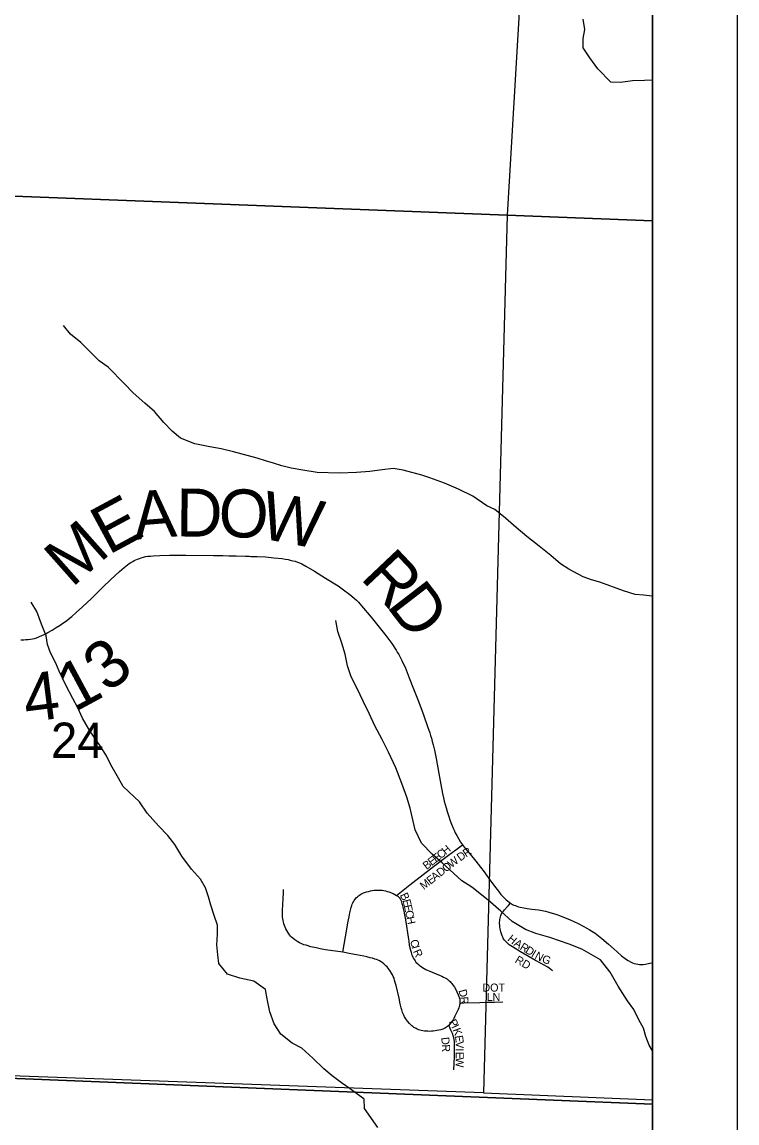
# Model space of a CAD drawing. Extents: x 0 to 34, y 0 to 22.
# Drawn here: x 30.071 to 30.917, y 18.143 to 19.446 of the extents above; entities that cross this region are included whole.
import ezdxf

# ---------------------------------------------------------------- set-up
doc = ezdxf.new("R2010")
doc.units = 0
for name, color, linetype in [('GM_X_Adjacent_County', 7, 'Continuous'), ('GM_X_County', 7, 'Continuous'), ('GM_X_County_Road', 7, 'Continuous'), ('GM_X_Minor_River', 7, 'Continuous'), ('GM_X_Section', 7, 'Continuous'), ('GM_X_Section_Text', 7, 'Continuous'), ('GM_X_Township', 7, 'Continuous'), ('GM_X_Township_Road', 7, 'Continuous'), ('GM_X_Township_Road_Text', 7, 'Continuous'), ('GM_X_Township_Subdivision', 7, 'Continuous'), ('GM_X_Township_Subdivision_Text', 7, 'Continuous'), ('SH_Data', 7, 'Continuous')]:
    doc.layers.add(name, color=color, linetype=linetype)

msp = doc.modelspace()

# ---------------------------------------------------------------- linework, layer by layer
at = {"layer": 'GM_X_Adjacent_County'}
msp.add_lwpolyline([(28.5181, 14.1), (30.8167, 14.1), (30.8167, 20.9), (28.7526, 20.9)], dxfattribs=at)
at = {"layer": 'GM_X_County'}
msp.add_lwpolyline([(28.5181, 14.1), (30.8167, 14.1), (30.8167, 20.9), (28.7526, 20.9)], dxfattribs=at)
at = {"layer": 'GM_X_County_Road'}
for points in [[(30.5918, 18.472), (30.5956, 18.4674), (30.6008, 18.4612), (30.6077, 18.4527), (30.6131, 18.4459), (30.6175, 18.4401), (30.6231, 18.4324), (30.6298, 18.4232), (30.6344, 18.4172), (30.6374, 18.4135), (30.6401, 18.4105), (30.6424, 18.4081), (30.6436, 18.407), (30.645, 18.4059), (30.6472, 18.4042), (30.6489, 18.4031)], [(30.6489, 18.4031), (30.6498, 18.4025), (30.6511, 18.4017), (30.6528, 18.4009), (30.6545, 18.4002), (30.6563, 18.3995), (30.6581, 18.3989), (30.6603, 18.3984), (30.6643, 18.3976), (30.6686, 18.3969), (30.6739, 18.3961), (30.6817, 18.3951), (30.6841, 18.3947), (30.6861, 18.3944), (30.6882, 18.394), (30.6903, 18.3935), (30.6928, 18.3929), (30.6954, 18.3921), (30.7024, 18.39), (30.7066, 18.3885), (30.7113, 18.3867), (30.7187, 18.3837), (30.7288, 18.3791), (30.7347, 18.3761), (30.739, 18.3736), (30.7419, 18.372), (30.745, 18.3701), (30.7487, 18.3675), (30.7527, 18.3645), (30.7569, 18.3612), (30.7645, 18.3546), (30.7713, 18.3486), (30.7748, 18.3454), (30.7802, 18.3409), (30.7843, 18.3377), (30.7859, 18.3366), (30.7879, 18.3353), (30.7905, 18.3338), (30.7931, 18.3327), (30.7952, 18.3319), (30.7972, 18.3314), (30.7993, 18.3309), (30.8014, 18.3306), (30.8036, 18.3304), (30.8058, 18.3305), (30.8084, 18.3308), (30.8137, 18.332), (30.8165, 18.3326), (30.8167, 18.3326)]]:
    msp.add_lwpolyline(points, dxfattribs=at)
at = {"layer": 'GM_X_Minor_River'}
for points in [[(30.8167, 19.3774), (30.8071, 19.377), (30.7931, 19.3765), (30.7787, 19.3744), (30.7673, 19.3747), (30.752, 19.3908), (30.7425, 19.4036), (30.7348, 19.4157), (30.7347, 19.4267), (30.7365, 19.4373), (30.7345, 19.4494)], [(30.3062, 18.941), (30.2929, 18.9432), (30.2751, 18.9468), (30.2584, 18.9534), (30.2485, 18.9617), (30.2385, 18.9722), (30.2274, 18.9849), (30.216, 18.9951), (30.2023, 19.007), (30.1919, 19.0179), (30.1725, 19.0374), (30.1622, 19.0449), (30.1503, 19.0569), (30.1404, 19.0667), (30.1282, 19.0768), (30.1198, 19.0869)], [(30.8167, 18.7665), (30.8165, 18.7665), (30.8059, 18.7676), (30.7964, 18.7686), (30.7824, 18.773), (30.7546, 18.783), (30.7444, 18.7859), (30.7345, 18.7892), (30.7178, 18.7985), (30.7079, 18.8049), (30.6964, 18.8146), (30.6827, 18.8258), (30.6682, 18.837), (30.6556, 18.8479), (30.6427, 18.8588), (30.6301, 18.8689), (30.6206, 18.8733), (30.6042, 18.8849), (30.5871, 18.8931), (30.5708, 18.9001), (30.5533, 18.9064), (30.5438, 18.9097), (30.5218, 18.9155), (30.5097, 18.9177), (30.4968, 18.916), (30.4821, 18.914), (30.4666, 18.9127), (30.4465, 18.9121), (30.42, 18.913), (30.4029, 18.9155), (30.3893, 18.918), (30.3783, 18.9209), (30.3684, 18.9238), (30.3589, 18.9268), (30.3491, 18.9297), (30.321, 18.9374), (30.3062, 18.941)], [(30.3283, 18.3144), (30.3138, 18.3192), (30.3035, 18.3316), (30.3023, 18.3418), (30.3014, 18.3539), (30.302, 18.3664), (30.3019, 18.377), (30.298, 18.3884), (30.2942, 18.4008), (30.2914, 18.4107), (30.2879, 18.4212), (30.2818, 18.4314), (30.2714, 18.4434), (30.2599, 18.4588), (30.2515, 18.4724), (30.2431, 18.4833), (30.2323, 18.4946), (30.219, 18.5096), (30.2098, 18.5232), (30.1903, 18.5411), (30.1849, 18.5509), (30.176, 18.5668), (30.1706, 18.5777), (30.1633, 18.5894), (30.1511, 18.6071), (30.1422, 18.6221), (30.1368, 18.6342), (30.1307, 18.6455), (30.1226, 18.661), (30.1148, 18.6776), (30.1106, 18.6874), (30.1044, 18.6995), (30.1009, 18.7093), (30.0993, 18.7195), (30.0939, 18.7335), (30.0881, 18.7482), (30.0815, 18.7595)], [(30.8167, 18.2282), (30.8127, 18.2352), (30.8088, 18.2454), (30.8061, 18.2552), (30.8007, 18.265), (30.7945, 18.2774), (30.7872, 18.2876), (30.7761, 18.3049), (30.7665, 18.3215), (30.755, 18.3362), (30.7333, 18.3488), (30.7181, 18.3547), (30.6953, 18.3625), (30.6786, 18.3672), (30.6665, 18.372), (30.6505, 18.3813), (30.6371, 18.3937), (30.6222, 18.4068), (30.6028, 18.4222), (30.591, 18.4296), (30.5815, 18.4382), (30.5677, 18.451), (30.5559, 18.4611), (30.5433, 18.4742), (30.5359, 18.4901), (30.53, 18.5154), (30.5261, 18.5286), (30.5203, 18.5449), (30.5129, 18.5634), (30.5044, 18.5818), (30.4967, 18.5969), (30.4882, 18.6131), (30.4817, 18.6267), (30.4743, 18.6422), (30.4674, 18.6573), (30.4601, 18.6712), (30.4558, 18.6841), (30.453, 18.698), (30.4491, 18.7109), (30.4444, 18.7245), (30.4421, 18.7377)], [(30.4919, 18.1375), (30.4758, 18.1601), (30.4757, 18.1711), (30.4589, 18.1834), (30.4486, 18.1905), (30.4379, 18.1988), (30.428, 18.207), (30.4147, 18.2198), (30.4017, 18.2314), (30.3903, 18.2373), (30.3769, 18.2482), (30.3689, 18.2602), (30.3638, 18.2746), (30.3607, 18.2901), (30.359, 18.3011), (30.3449, 18.3108), (30.3283, 18.3144)]]:
    msp.add_lwpolyline(points, dxfattribs=at)
at = {"layer": 'GM_X_Section'}
for p, q in [((30.8167, 19.2109), (30.8167, 20.2305)), ((30.8167, 18.1704), (30.8167, 19.2109))]:
    msp.add_line(p, q, dxfattribs=at)
for points in [[(30.7049, 20.2326), (30.6447, 19.2173), (29.6621, 19.2554), (29.7299, 20.2792)], [(30.6447, 19.2173), (30.6169, 18.1787), (29.6404, 18.2139), (29.6621, 19.2554)]]:
    msp.add_lwpolyline(points, close=True, dxfattribs=at)
for points in [[(30.8167, 20.2305), (30.7049, 20.2326), (30.6447, 19.2173), (30.8167, 19.2109)], [(30.8167, 19.2109), (30.6447, 19.2173), (30.6169, 18.1787), (30.8167, 18.1704)]]:
    msp.add_lwpolyline(points, dxfattribs=at)
at = {"layer": 'GM_X_Township'}
for points in [[(28.7526, 20.9), (28.7366, 20.4185), (28.7263, 19.9342), (28.6656, 18.2443), (29.0347, 18.2309), (29.9568, 18.1999), (30.8167, 18.1651)], [(30.8167, 18.1651), (30.8167, 20.9), (28.7526, 20.9)], [(30.8167, 18.1651), (29.9568, 18.1999), (29.0347, 18.2309), (28.6656, 18.2443), (28.6433, 17.8576), (28.637, 17.506), (28.6368, 17.4981), (28.5999, 16.6109), (28.5991, 16.5887), (28.5955, 16.4142)], [(28.5181, 14.1), (30.8167, 14.1), (30.8167, 18.1651)]]:
    msp.add_lwpolyline(points, dxfattribs=at)
at = {"layer": 'GM_X_Township_Road'}
for points in [[(30.0692, 18.715), (30.0728, 18.715), (30.0754, 18.7151), (30.0781, 18.7153), (30.0807, 18.7157), (30.0831, 18.7161), (30.0856, 18.7166), (30.0878, 18.7173), (30.0908, 18.7184), (30.0951, 18.7202), (30.0981, 18.7217), (30.1014, 18.7234), (30.1064, 18.7262), (30.1112, 18.7293), (30.1158, 18.7323), (30.1192, 18.7346), (30.1233, 18.7375), (30.1266, 18.7399), (30.1297, 18.7424), (30.1349, 18.747), (30.1423, 18.7537), (30.1528, 18.7638), (30.1666, 18.7774), (30.1755, 18.786), (30.1859, 18.7957), (30.1916, 18.8005), (30.1976, 18.805), (30.1995, 18.8063), (30.2017, 18.8077), (30.2036, 18.8087), (30.2056, 18.8097), (30.2075, 18.8105), (30.2096, 18.8112), (30.2118, 18.812), (30.2143, 18.8126), (30.217, 18.8133), (30.2198, 18.8137), (30.2226, 18.814), (30.2259, 18.8142), (30.234, 18.8146), (30.2452, 18.8149), (30.2644, 18.8149), (30.2973, 18.8146), (30.3085, 18.8145), (30.3153, 18.8144), (30.324, 18.8141), (30.3352, 18.8138), (30.3395, 18.8137), (30.3414, 18.8136), (30.3488, 18.8134), (30.3587, 18.8129), (30.3685, 18.812), (30.3784, 18.8109), (30.3821, 18.8104), (30.3856, 18.8098), (30.3881, 18.8092), (30.3912, 18.8085), (30.3938, 18.8078), (30.3965, 18.8069), (30.399, 18.8059), (30.4017, 18.8047), (30.4066, 18.8021), (30.4168, 18.7962), (30.43, 18.788), (30.4447, 18.7787), (30.4513, 18.7741), (30.4587, 18.7685), (30.4639, 18.764), (30.4664, 18.7617), (30.4688, 18.7593), (30.4726, 18.7552), (30.4837, 18.7418), (30.4918, 18.7318), (30.5012, 18.72), (30.5082, 18.7105), (30.5133, 18.7027), (30.5148, 18.7004), (30.5165, 18.6974), (30.5183, 18.6942), (30.5203, 18.6903), (30.5219, 18.6868), (30.5239, 18.6824), (30.529, 18.6697), (30.5341, 18.657), (30.5388, 18.645), (30.5427, 18.6347), (30.5458, 18.6259), (30.5507, 18.6123), (30.5532, 18.6048), (30.5541, 18.6017), (30.5551, 18.5986), (30.5562, 18.5944), (30.5572, 18.5905), (30.558, 18.5873), (30.5586, 18.5843), (30.5606, 18.5744), (30.5638, 18.5566), (30.5662, 18.5436), (30.5683, 18.533), (30.5694, 18.5278), (30.5704, 18.5239), (30.5714, 18.52), (30.5725, 18.516), (30.5739, 18.5116), (30.5758, 18.5057), (30.5771, 18.5017), (30.579, 18.4968)], [(30.579, 18.4968), (30.5791, 18.4965), (30.5809, 18.4921), (30.5821, 18.4894), (30.5834, 18.4864), (30.5852, 18.4831), (30.5872, 18.4796), (30.5897, 18.4754), (30.5918, 18.472)]]:
    msp.add_lwpolyline(points, dxfattribs=at)
at = {"layer": 'GM_X_Township_Subdivision'}
for points in [[(30.514, 18.4124), (30.5298, 18.4249), (30.5578, 18.4466), (30.5752, 18.46), (30.584, 18.4664), (30.5918, 18.472)], [(30.4503, 18.345), (30.4297, 18.348), (30.4236, 18.3491), (30.4188, 18.3501), (30.4126, 18.3516), (30.4068, 18.3533), (30.4043, 18.354), (30.402, 18.3549), (30.3992, 18.3562), (30.3969, 18.3575), (30.3936, 18.3598), (30.391, 18.3618), (30.3897, 18.363), (30.3886, 18.3642), (30.3873, 18.3658), (30.3864, 18.367), (30.3852, 18.3687), (30.3841, 18.3706), (30.383, 18.3727), (30.3821, 18.3747), (30.3813, 18.3768), (30.3807, 18.3787), (30.3801, 18.3809), (30.3797, 18.3828), (30.3794, 18.3847), (30.3791, 18.3865), (30.3789, 18.3888), (30.3789, 18.3909), (30.379, 18.3948), (30.3793, 18.401), (30.3799, 18.4092), (30.38, 18.4149), (30.38, 18.4195)], [(30.4503, 18.345), (30.4549, 18.3724), (30.4562, 18.3797), (30.4577, 18.387), (30.4587, 18.3918), (30.4603, 18.3982), (30.461, 18.4003), (30.4615, 18.4019), (30.4622, 18.4035), (30.4629, 18.4048), (30.4638, 18.4063), (30.4651, 18.408), (30.4666, 18.4097), (30.4677, 18.4108), (30.4689, 18.4118), (30.4702, 18.4127), (30.4715, 18.4136), (30.4731, 18.4144), (30.4749, 18.4152), (30.4783, 18.4165), (30.4807, 18.4171), (30.4831, 18.4177), (30.4852, 18.418), (30.4874, 18.4184), (30.4894, 18.4185), (30.4917, 18.4187), (30.4942, 18.4186), (30.4967, 18.4184), (30.4988, 18.4181), (30.5009, 18.4177), (30.5027, 18.4171), (30.5046, 18.4165), (30.5099, 18.4144), (30.512, 18.4134), (30.514, 18.4124)], [(30.514, 18.4124), (30.5155, 18.4113), (30.5167, 18.4101), (30.5174, 18.4093), (30.518, 18.4084), (30.5186, 18.4073), (30.5192, 18.406), (30.5197, 18.4045), (30.5202, 18.4029), (30.5208, 18.4008), (30.5214, 18.3984), (30.5224, 18.3938), (30.5234, 18.3893), (30.5242, 18.3853), (30.5249, 18.3812), (30.5275, 18.363), (30.5283, 18.3582), (30.529, 18.3535), (30.5304, 18.3474), (30.531, 18.3451), (30.5317, 18.3427), (30.5324, 18.3411), (30.5333, 18.3393), (30.5341, 18.3377), (30.5351, 18.336), (30.5358, 18.3349), (30.5369, 18.3335), (30.5391, 18.3313), (30.5405, 18.3299), (30.5419, 18.3289), (30.5445, 18.3271), (30.5487, 18.3248), (30.5562, 18.3213), (30.5654, 18.3175), (30.5674, 18.3167), (30.5696, 18.3156), (30.5728, 18.3139), (30.5743, 18.3129), (30.5751, 18.3123), (30.5761, 18.3114), (30.5772, 18.3105), (30.5783, 18.3093), (30.5793, 18.3081), (30.5802, 18.3069), (30.5813, 18.3053), (30.5824, 18.3036), (30.5839, 18.301), (30.5853, 18.2983), (30.5868, 18.2947), (30.5876, 18.2928), (30.5881, 18.2912), (30.5886, 18.2895), (30.5889, 18.2881), (30.5889, 18.2874), (30.5889, 18.2865), (30.5888, 18.2849)], [(30.6983, 18.3231), (30.6965, 18.3247), (30.6946, 18.3262), (30.6929, 18.3274), (30.6843, 18.332), (30.6782, 18.3353), (30.6604, 18.3455), (30.6509, 18.3514), (30.6473, 18.3539), (30.6445, 18.3564), (30.6424, 18.3586), (30.6413, 18.3599), (30.6406, 18.3611), (30.6396, 18.3628), (30.6388, 18.3644), (30.638, 18.3667), (30.6375, 18.3682), (30.6372, 18.3694), (30.6369, 18.371), (30.6366, 18.3727), (30.6362, 18.3751), (30.636, 18.377), (30.6358, 18.3791), (30.6358, 18.3807), (30.6359, 18.3824), (30.6361, 18.3837), (30.6364, 18.3853), (30.6367, 18.3868), (30.6373, 18.3884), (30.6378, 18.3896), (30.6385, 18.391), (30.6394, 18.3923), (30.6403, 18.3937), (30.6417, 18.3953), (30.645, 18.399), (30.6465, 18.4005), (30.6489, 18.4031)], [(30.5756, 18.2584), (30.5742, 18.2572), (30.5731, 18.2564), (30.572, 18.2557), (30.5709, 18.255), (30.5696, 18.2544), (30.5685, 18.254), (30.5673, 18.2536), (30.5661, 18.2533), (30.564, 18.2528), (30.5616, 18.2523), (30.5596, 18.252), (30.5573, 18.2517), (30.5552, 18.2515), (30.5528, 18.2514), (30.5508, 18.2515), (30.5489, 18.2516), (30.5471, 18.2518), (30.5449, 18.2521), (30.5429, 18.2525), (30.5399, 18.2534), (30.5383, 18.254), (30.537, 18.2546), (30.5356, 18.2554), (30.5344, 18.2561), (30.5331, 18.2571), (30.5319, 18.258), (30.5292, 18.2606), (30.5268, 18.2634), (30.5256, 18.265), (30.5247, 18.2664), (30.5234, 18.2685), (30.5224, 18.2704), (30.5211, 18.2738), (30.5201, 18.2768), (30.5194, 18.2792), (30.5183, 18.2838), (30.5168, 18.2906), (30.5134, 18.3057), (30.5124, 18.3094), (30.5116, 18.3121), (30.5109, 18.3142), (30.51, 18.3163), (30.509, 18.3183), (30.5079, 18.3202), (30.5059, 18.3234), (30.5048, 18.3251), (30.5039, 18.3263), (30.5026, 18.3278), (30.5013, 18.3291), (30.4987, 18.3313), (30.4969, 18.3328), (30.4955, 18.3337), (30.4938, 18.3347), (30.4922, 18.3355), (30.4901, 18.3364), (30.4882, 18.337), (30.4854, 18.3379), (30.4828, 18.3386), (30.4788, 18.3396), (30.475, 18.3405), (30.4665, 18.3421), (30.4599, 18.3433), (30.4503, 18.345)], [(30.5888, 18.2849), (30.5886, 18.2837), (30.5883, 18.2824), (30.5874, 18.2794), (30.5866, 18.2772), (30.5854, 18.2741), (30.583, 18.2692), (30.5817, 18.2668), (30.5807, 18.265), (30.5796, 18.2633), (30.5781, 18.2615), (30.5767, 18.2597), (30.5756, 18.2584)], [(30.5888, 18.2849), (30.5935, 18.285), (30.6125, 18.2855), (30.6213, 18.2858), (30.6298, 18.286), (30.6395, 18.2862)], [(30.5817, 18.2057), (30.5823, 18.2213), (30.5825, 18.2298), (30.5826, 18.2336), (30.5825, 18.2366), (30.5823, 18.2389), (30.5819, 18.2417), (30.5815, 18.2438), (30.5808, 18.2463), (30.5803, 18.2481), (30.5797, 18.2496), (30.579, 18.2513), (30.5783, 18.2529), (30.5775, 18.2546), (30.5769, 18.2559), (30.5756, 18.2584)]]:
    msp.add_lwpolyline(points, dxfattribs=at)
at = {"layer": 'SH_Data'}
for points in [[(23.9167, 21), (30.9167, 21), (30.9167, 14), (23.9167, 14)], [(24.0167, 20.9), (30.8167, 20.9), (30.8167, 14.1), (24.0167, 14.1)]]:
    msp.add_lwpolyline(points, close=True, dxfattribs=at)

# ---------------------------------------------------------------- texts
at = {"layer": 'GM_X_Section_Text'}
msp.add_text('24', height=0.04186, rotation=0, dxfattribs=at).set_placement((30.105, 18.575))
at = {"layer": 'GM_X_Township_Road_Text'}
for s, rotation, p in [('E', 28.319, (30.173, 18.8148)), ('A', 4.6605, (30.2045, 18.8332)), ('D', 359.6066, (30.253, 18.8372)), ('O', 358.2621, (30.3027, 18.8369)), ('W', 349.2186, (30.3503, 18.8356)), ('M', 41.5477, (30.1297, 18.7758)), ('R', 313.446, (30.4699, 18.7878)), ('D', 307.6386, (30.501, 18.7551)), ('3', 38.3371, (30.1721, 18.6511)), ('1', 28.3389, (30.1323, 18.6285)), ('4', 7.1335, (30.0759, 18.6172))]:
    msp.add_text(s, height=0.0568, rotation=rotation, dxfattribs=at).set_placement(p)
at = {"layer": 'GM_X_Township_Subdivision_Text'}
for s, rotation, p in [('C', 37.5502, (30.5659, 18.455)), ('H', 39.5352, (30.5721, 18.4598)), ('R', 32.8549, (30.5961, 18.4571)), ('B', 37.4916, (30.5494, 18.4423)), ('E', 37.5106, (30.5553, 18.4469)), ('E', 37.5036, (30.5606, 18.4509)), ('W', 37.4415, (30.5788, 18.4444)), ('D', 35.3268, (30.5894, 18.4524)), ('A', 38.1683, (30.5592, 18.4289)), ('D', 38.1511, (30.5657, 18.4341)), ('O', 38.1376, (30.5723, 18.4392)), ('M', 38.1449, (30.5461, 18.4186)), ('E', 38.1806, (30.554, 18.4248)), ('B', 295.479, (30.5177, 18.4128)), ('E', 284.414, (30.5208, 18.4065)), ('E', 282.1406, (30.5224, 18.4002)), ('C', 282.01, (30.5238, 18.3936)), ('H', 281.9787, (30.5254, 18.3863)), ('H', 320.6337, (30.6444, 18.3595)), ('C', 285.1316, (30.5297, 18.3588)), ('I', 285.1347, (30.5316, 18.3516)), ('R', 293.1474, (30.5332, 18.3462)), ('A', 327.6622, (30.6519, 18.3534)), ('R', 328.2889, (30.659, 18.3489)), ('D', 328.2565, (30.6654, 18.345)), ('I', 328.2494, (30.6725, 18.3406)), ('RD', 329.5361, (30.6532, 18.3335)), ('N', 331.7983, (30.6766, 18.3381)), ('G', 338.9368, (30.6851, 18.3336)), ('D', 284.4921, (30.5871, 18.2998)), ('DOT', 0, (30.6155, 18.2985)), ('LN', 0, (30.6205, 18.2874)), ('R', 274.2534, (30.5891, 18.2922)), ('P', 298.9724, (30.5753, 18.2626)), ('I', 295.3337, (30.5785, 18.2569)), ('D', 277.5614, (30.5666, 18.244)), ('K', 289.6862, (30.5802, 18.2534)), ('E', 278.1958, (30.5829, 18.246)), ('R', 270.85, (30.5677, 18.236)), ('V', 270.8525, (30.5838, 18.2397)), ('I', 270, (30.5839, 18.2315)), ('E', 269.9942, (30.5839, 18.2273)), ('W', 269.9975, (30.5839, 18.2206))]:
    msp.add_text(s, height=0.00947, rotation=rotation, dxfattribs=at).set_placement(p)

doc.saveas('drawing.dxf')
